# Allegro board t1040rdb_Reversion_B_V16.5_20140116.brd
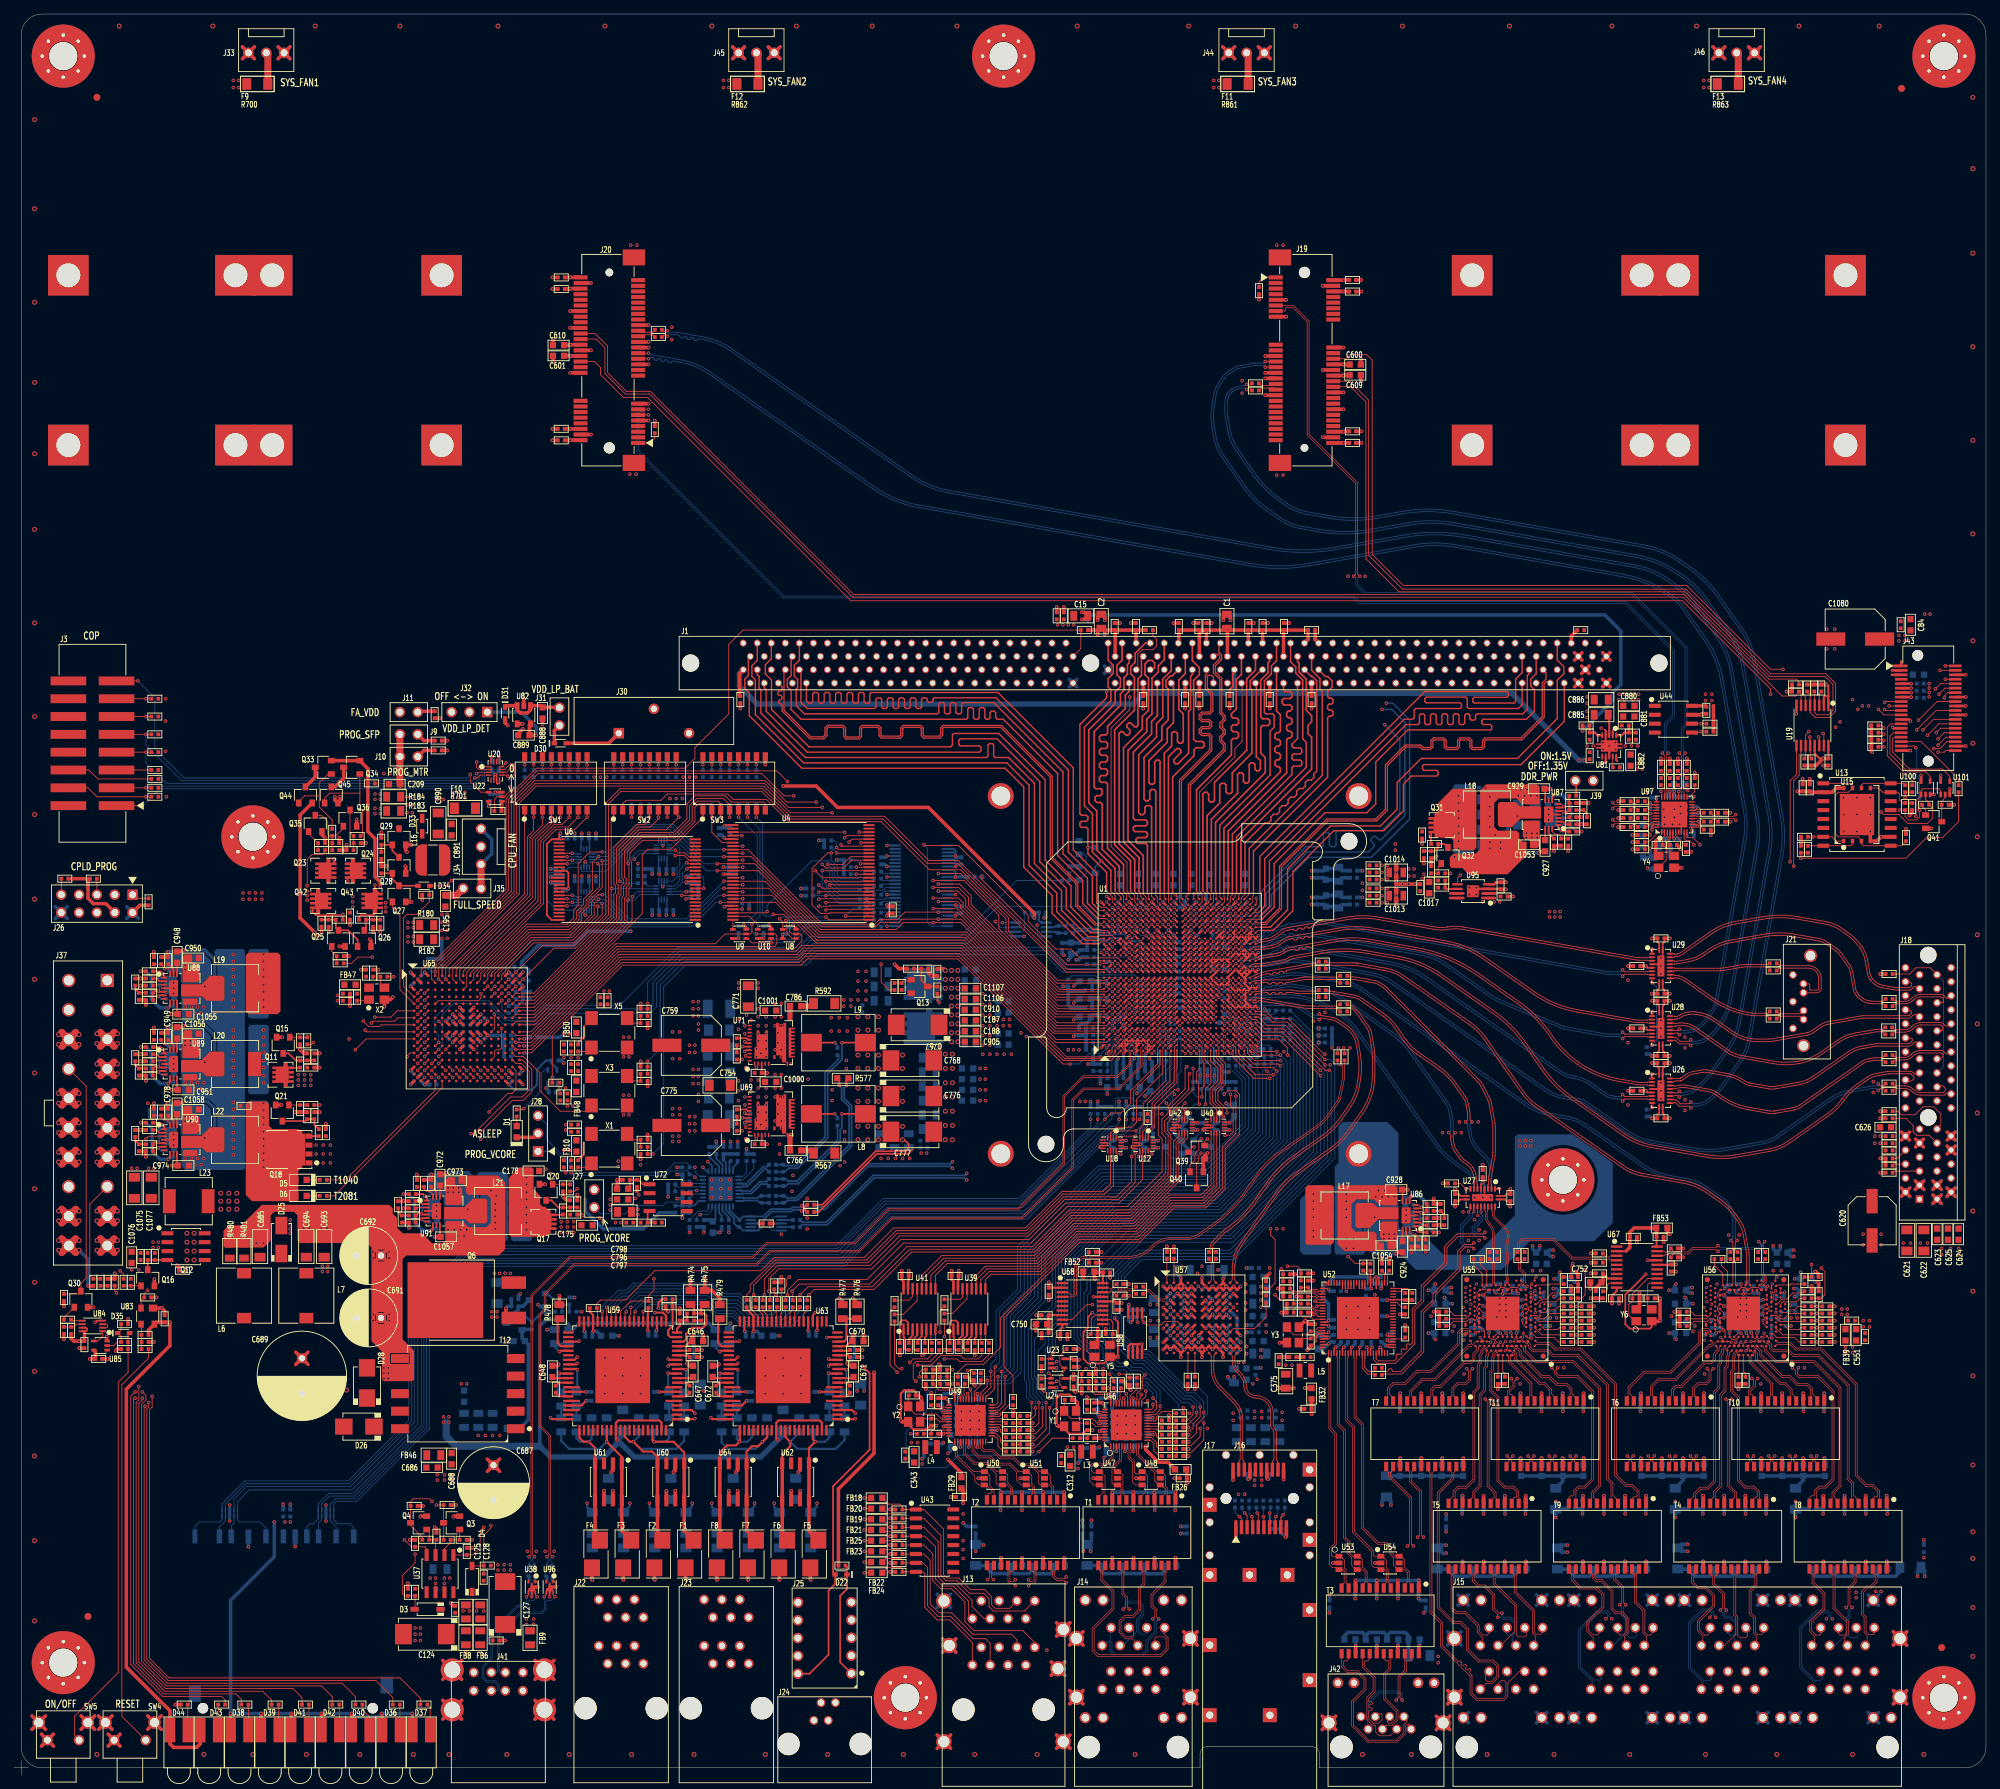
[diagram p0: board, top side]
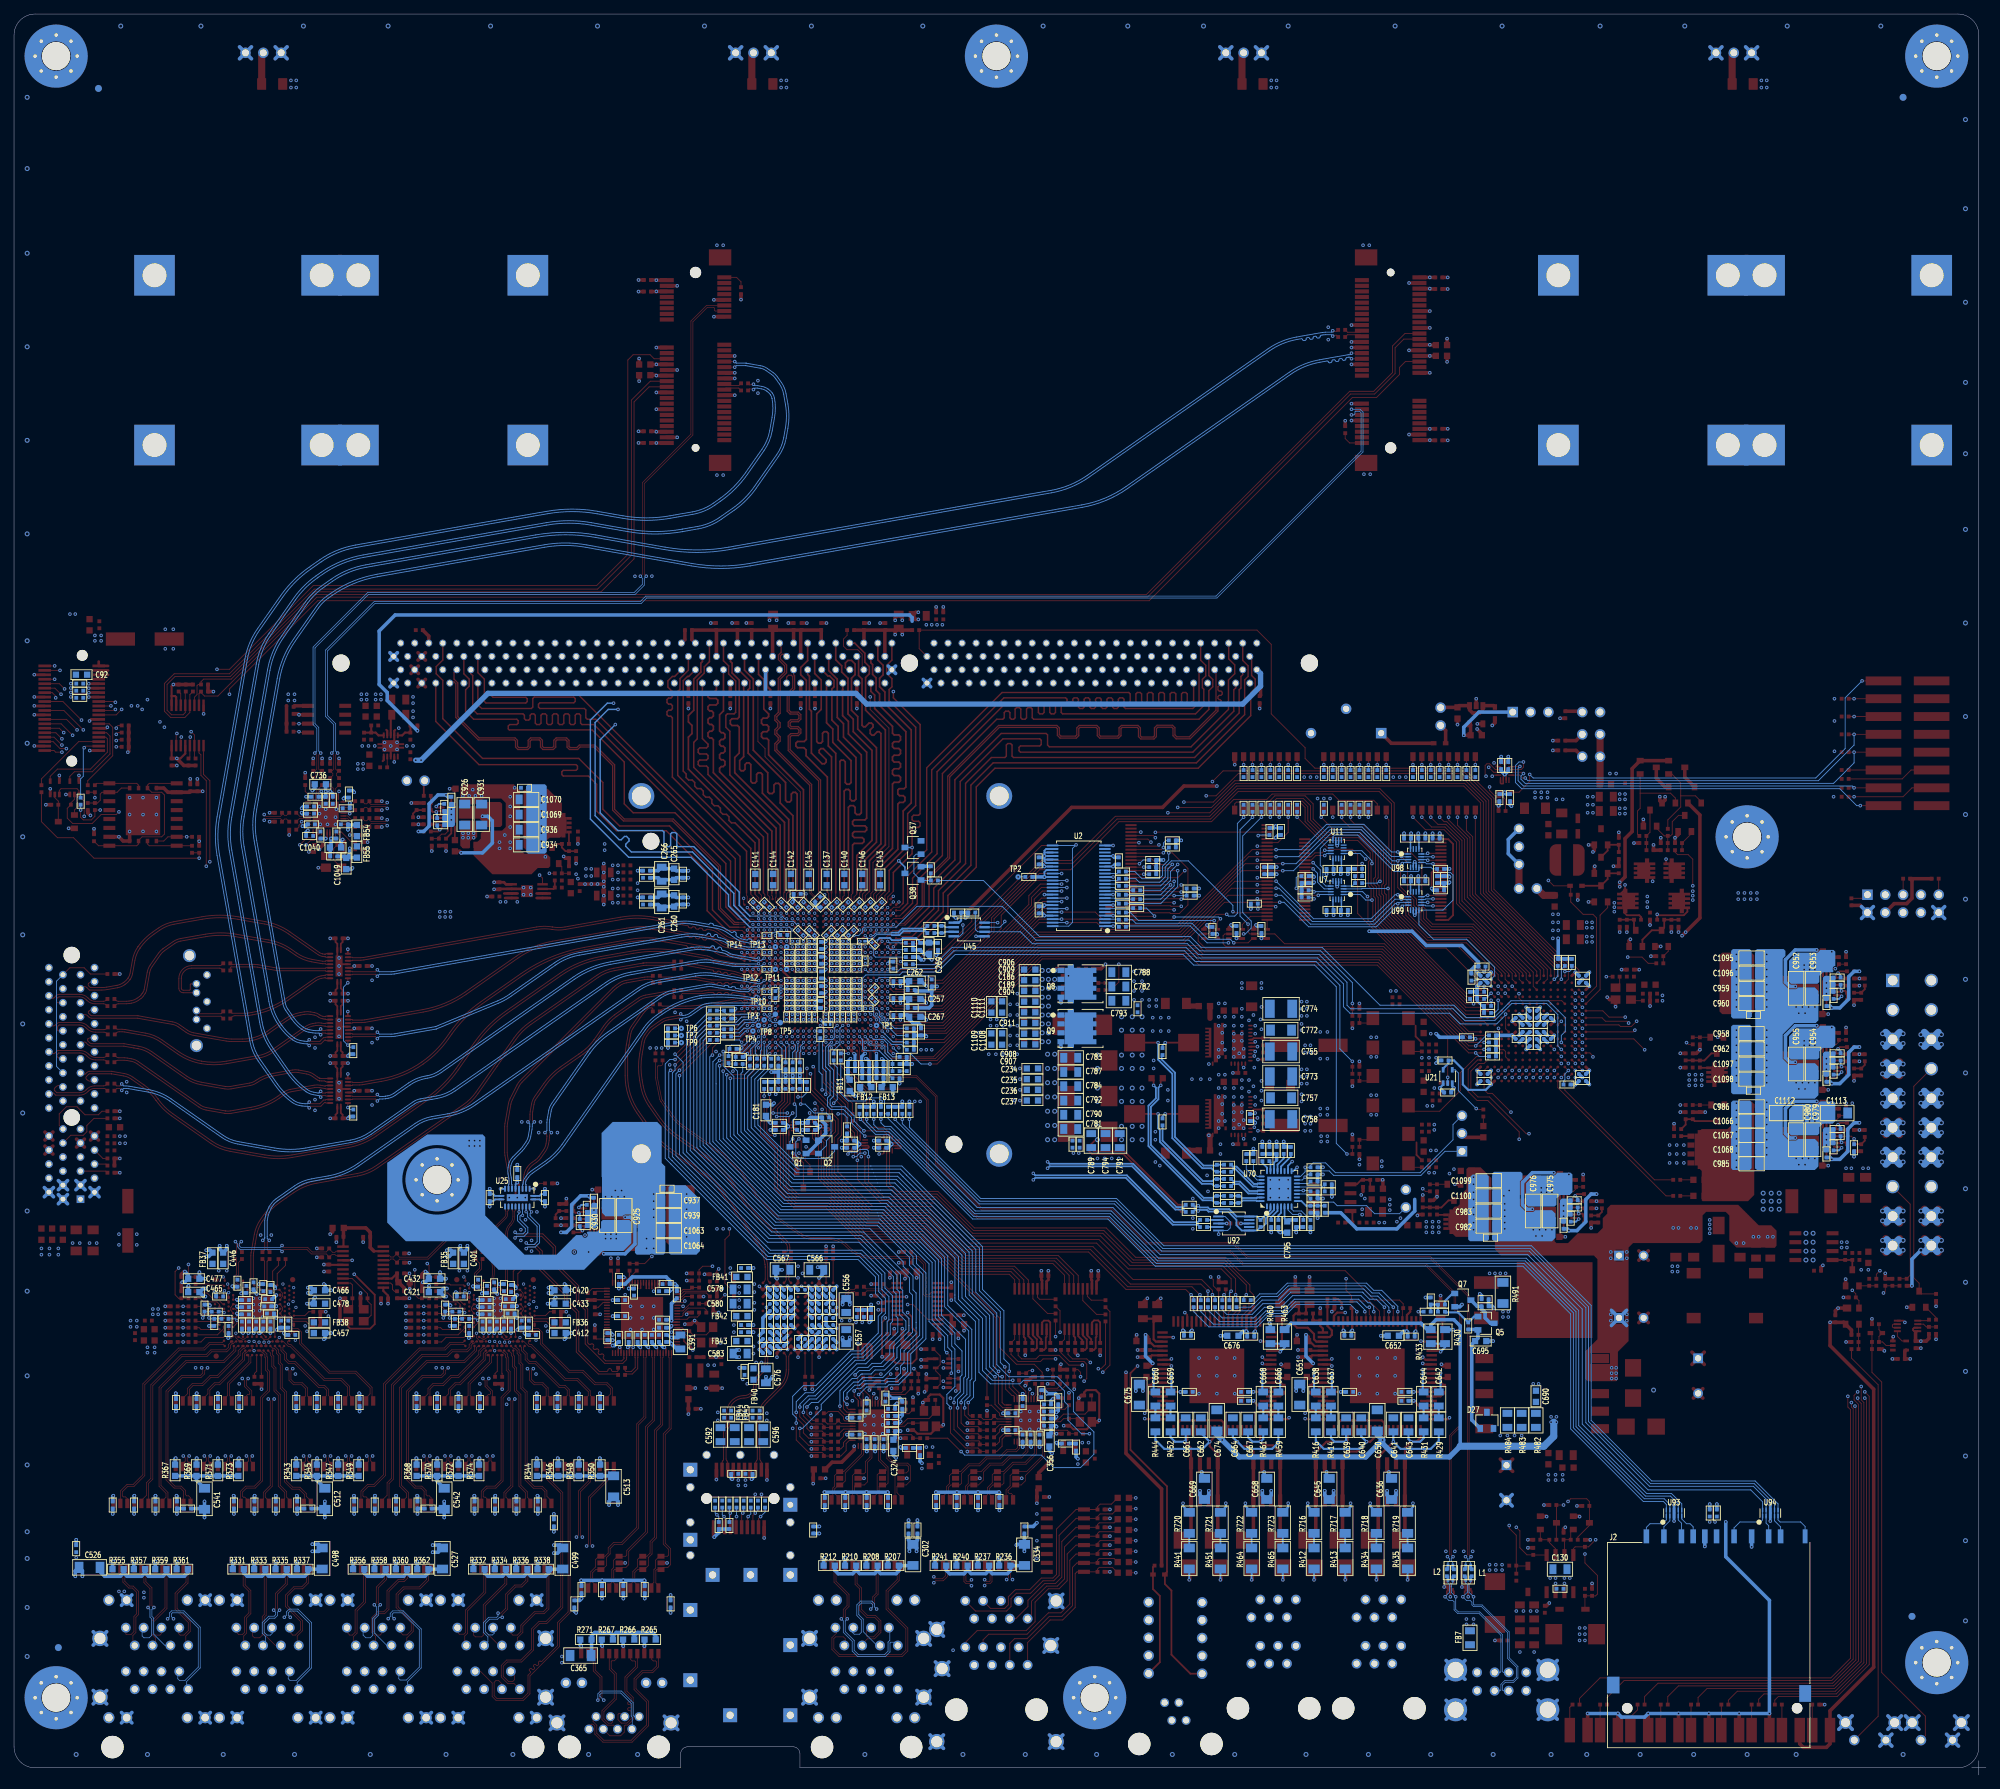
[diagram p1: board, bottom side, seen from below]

Outline 281.02 x 251.02 mm; copper layers: TOP, L2GND, L3SIG, L4PWR, L5PWR, L6SIG, L7GND, BOTTOM. Coordinates in mm from the lower left corner of the outline.
Outline path: 0,1.02 2.03,1.02 ; 1.02,2.03 1.02,0 ; 1.02,248.02 arc(1.89,250.14) 4.02,251.02 278.02,251.02 arc(280.14,250.14) 281.02,248.02 281.02,4.02 arc(280.14,1.89) 278.02,1.02 186.02,1.02 186.02,3.02 arc(185.72,3.72) 185.02,4.02 170.02,4.02 arc(169.31,3.72) 169.02,3.02 169.02,1.02 4.02,1.02 arc(1.89,1.89) 1.02,4.02 1.02,248.02

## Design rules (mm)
net group 1V05_EC1_AVDD: nets 1V05_EC1_DVDD N16973842
net group 1V05_EC2_AVDD: nets 1V05_EC2_DVDD N16880820
net group 1V05_SG_AVDD: nets 1V05_SG_DVDD N16909742
net group 1V8_0641_VDD: nets 1V8_0641_VDDA 1V8_0641_VDDXTAL
net group CKE_ISO_EN: nets CKE_ISO_EN N20553507
net group CPLD_REFCLK: nets CPLD_REFCLK N19163046
net group DDR_REFCLK: nets DDR_REFCLK N17232338
net group DDRPWR_EN_N: nets DDRPWR_EN_N N19623885
net group EC1_GTXCLK: nets EC1_GTXCLK N17060054
net group EC1_INT_N: nets EC1_INT_N N16974631
net group EC1_LED0: nets EC1_LED0 N16974572
net group EC1_LED1: nets EC1_LED1 N16974538
net group EC1_MDI0: nets EC1_MDI0_N EC1_MDI0_P
net group EC1_MDI1: nets EC1_MDI1_N EC1_MDI1_P
net group EC1_MDI2: nets EC1_MDI2_N EC1_MDI2_P
net group EC1_MDI3: nets EC1_MDI3_N EC1_MDI3_P
net group EC1_MDX0: nets EC1_MDX0_N EC1_MDX0_P
net group EC1_MDX1: nets EC1_MDX1_N EC1_MDX1_P
net group EC1_MDX2: nets EC1_MDX2_N EC1_MDX2_P
net group EC1_MDX3: nets EC1_MDX3_N EC1_MDX3_P
net group EC1_PME_N: nets EC1_PME_N N16975158
net group EC1_REFCLK: nets EC1_REFCLK N16975047
net group EC1_RST_N: nets EC1_RST_N N16974885
net group EC1_RXCLK: nets EC1_RXCLK N16974061
net group EC1_RXCTL: nets EC1_RXCTL N16974138
net group EC1_RXD0: nets EC1_RXD0 N16974094
net group EC1_RXD1: nets EC1_RXD1 N16974110
net group EC1_RXD2: nets EC1_RXD2 N16974123
net group EC1_RXD3: nets EC1_RXD3 N16974136
net group EC1_TXCTL: nets EC1_TXCTL N17059985
net group EC1_TXD0: nets EC1_TXD0 N17059735
net group EC1_TXD1: nets EC1_TXD1 N17059733
net group EC1_TXD2: nets EC1_TXD2 N17059734
net group EC1_TXD3: nets EC1_TXD3 N17059732
net group EC2_GTXCLK: nets EC2_GTXCLK N17059152
net group EC2_INT_N: nets EC2_INT_N N16871038
net group EC2_LED0: nets EC2_LED0 N16870890
net group EC2_LED1: nets EC2_LED1 N16870844
net group EC2_MDI0: nets EC2_MDI0_N EC2_MDI0_P
net group EC2_MDI1: nets EC2_MDI1_N EC2_MDI1_P
net group EC2_MDI2: nets EC2_MDI2_N EC2_MDI2_P
net group EC2_MDI3: nets EC2_MDI3_N EC2_MDI3_P
net group EC2_MDX0: nets EC2_MDX0_N EC2_MDX0_P
net group EC2_MDX1: nets EC2_MDX1_N EC2_MDX1_P
net group EC2_MDX2: nets EC2_MDX2_N EC2_MDX2_P
net group EC2_MDX3: nets EC2_MDX3_N EC2_MDX3_P
net group EC2_PME_N: nets EC2_PME_N N16877780
net group EC2_REFCLK: nets EC2_REFCLK N16874872
net group EC2_RST_N: nets EC2_RST_N N16873350
net group EC2_RXCLK: nets EC2_RXCLK N16869850
net group EC2_RXCTL: nets EC2_RXCTL N16869978
net group EC2_RXD0: nets EC2_RXD0 N16869910
net group EC2_RXD1: nets EC2_RXD1 N16869938
net group EC2_RXD2: nets EC2_RXD2 N16869959
net group EC2_RXD3: nets EC2_RXD3 N16869976
net group EC2_TXCTL: nets EC2_TXCTL N17059149
net group EC2_TXD0: nets EC2_TXD0 N17059126
net group EC2_TXD1: nets EC2_TXD1 N17059132
net group EC2_TXD2: nets EC2_TXD2 N17059135
net group EC2_TXD3: nets EC2_TXD3 N17059138
net group EMI1_MDC_SLP: nets EMI1_MDC_SLP N17060498
net group EMI2_MDC: nets EMI2_MDC N17059643
net group EVDD_SEL: nets EVDD_SEL N20559490
net group FXO_LED: nets FXO_LED N18635664
net group FXS1_LED: nets FXS1_LED N18636371
net group FXS2_LED: nets FXS2_LED N18636375
net group FXS3_LED: nets FXS3_LED N18636077
net group FXS4_LED: nets FXS4_LED N18636082
net group IFC_A5: nets IFC_A5 N22257590
net group IFC_A6: nets IFC_A6 N22257592
net group IFC_A7: nets IFC_A7 N22257594
net group IFC_A8: nets IFC_A8 N22258216
net group IFC_A9: nets IFC_A9 N22258098
net group IFC_A10: nets IFC_A10 N22258100
net group IFC_A11: nets IFC_A11 N22258102
net group IFC_A12: nets IFC_A12 N22258104
net group IFC_A13: nets IFC_A13 N22258634
net group IFC_A14: nets IFC_A14 N22258636
net group IFC_A15: nets IFC_A15 N22258638
net group IFC_CLK: nets IFC_CLK N16821274
net group IOPWR_EN: nets IOPWR_EN N18273767
net group LED_STATUS: nets LED_STATUS N22361656
net group LED_T1040_DET: nets LED_T1040_DET N19293526
net group LED_T2081_DET: nets LED_T2081_DET N19295120
net group MPEX1_REFCLK_N: nets MPEX1_REFCLK_N N21105614
net group MPEX1_REFCLK_P: nets MPEX1_REFCLK_P N21105612
net group MPEX1_RX: nets MPEX1_RX_N MPEX1_RX_P
net group MPEX1_TX_N: nets MPEX1_TX_N N16984233
net group MPEX1_TX_P: nets MPEX1_TX_P N16984231
net group MPEX2_REFCLK_N: nets MPEX2_REFCLK_N N21105622
net group MPEX2_REFCLK_P: nets MPEX2_REFCLK_P N21105620
net group MPEX2_RX: nets MPEX2_RX_N MPEX2_RX_P
net group MPEX2_TX_N: nets MPEX2_TX_N N16985356
net group MPEX2_TX_P: nets MPEX2_TX_P N16985354
net group N16849665: nets N16849665 N16849667
net group N16849815: nets N16849815 N16849817
net group N16862407: nets N16862407 N16862837
net group N17055373: nets N17055373 N17055376
net group N17055394: nets N17055394 N17055396
net group N17055422: nets N17055422 N17055507
net group N17055459: nets N17055459 N17055529
net group N17055495: nets N17055419 N17055495
net group N17055527: nets N17055461 N17055527
net group N17056740: nets N17056740 N17056750
net group N17056764: nets N17056764 N17056766
net group N17056778: nets N17056778 N17056834
net group N17056796: nets N17056796 N17056846
net group N17056816: nets N17056776 N17056816
net group N17056844: nets N17056798 N17056844
net group N17321019: nets N17321001 N17321019
net group N17399246: nets N17399246 N17399288
net group N17401544: nets N17400346 N17401544
net group N17448841: nets N17448841 N17448842
net group N17448854: nets N17448854 N17448855
net group N17639958: nets N17639958 N17639964
net group N18271718: nets N18271718 N18271794
net group N18272050: nets N18272050 N18272126
net group N18272820: nets N18272820 N18272905
net group N18273181: nets N18273181 N18273262
net group N18562864: nets N17523697 N18562864
net group N18564716: nets N18564716 N18564801
net group N18566414: nets N18566414 N18566880
net group N18671728: nets N18671664 N18671728
net group N18671731: nets N18671661 N18671731
net group N19623883: nets N19623883 N19623968
net group N19645019: nets N19645019 N19645035
net group N19646930: nets N19646930 N19646940
net group N19648414: nets N19648414 N19648420
net group N19650272: nets N19650272 N19650282
net group N19651731: nets N19651731 N19651747
net group N19653218: nets N19653218 N19653234
net group N19673378: nets N19673378 N19673381
net group N19675149: nets N19675149 N19675151
net group N20559492: nets N20559492 N20559589
net group N20559669: nets N20559669 N20559724
net group N20562350: nets N17013374 N20562350
net group PEX_REFCLK_N: nets N22254282 PEX_REFCLK_N
net group PEX_REFCLK_P: nets N22254280 PEX_REFCLK_P
net group PEX_RX0: nets PEX_RX0_N PEX_RX0_P
net group PEX_RX1: nets PEX_RX1_N PEX_RX1_P
net group PEX_RX2: nets PEX_RX2_N PEX_RX2_P
net group PEX_RX3: nets PEX_RX3_N PEX_RX3_P
net group PEX_TX0_N: nets N16980532 PEX_TX0_N
net group PEX_TX0_P: nets N16980534 PEX_TX0_P
net group PEX_TX1_N: nets N16981085 PEX_TX1_N
net group PEX_TX1_P: nets N16981083 PEX_TX1_P
net group PEX_TX2_N: nets N16981144 PEX_TX2_N
net group PEX_TX2_P: nets N16981142 PEX_TX2_P
net group PEX_TX3_N: nets N16981215 PEX_TX3_N
net group PEX_TX3_P: nets N16981213 PEX_TX3_P
net group PROC_SPI_CLK: nets N17040696 PROC_SPI_CLK
net group PWR_GOOD: nets N18563122 PWR_GOOD
net group QSG1_INT_N: nets N17584869 QSG1_INT_N
net group QSG1_LED0: nets N17775429 QSG1_LED0
net group QSG1_LED1: nets N17775417 QSG1_LED1
net group QSG1_MDI0: nets QSG1_MDI0_N QSG1_MDI0_P
net group QSG1_MDI1: nets QSG1_MDI1_N QSG1_MDI1_P
net group QSG1_MDI2: nets QSG1_MDI2_N QSG1_MDI2_P
net group QSG1_MDI3: nets QSG1_MDI3_N QSG1_MDI3_P
net group QSG1_MDX0: nets QSG1_MDX0_N QSG1_MDX0_P
net group QSG1_MDX1: nets QSG1_MDX1_N QSG1_MDX1_P
net group QSG1_MDX2: nets QSG1_MDX2_N QSG1_MDX2_P
net group QSG1_MDX3: nets QSG1_MDX3_N QSG1_MDX3_P
net group QSG1_REFCLK_N: nets N17823659 QSG1_REFCLK_N
net group QSG1_REFCLK_P: nets N17823662 QSG1_REFCLK_P
net group QSG1_RST_N: nets N17629369 QSG1_RST_N
net group QSG2_INT_N: nets N17640717 QSG2_INT_N
net group QSG2_LED0: nets N17779761 QSG2_LED0
net group QSG2_LED1: nets N17779755 QSG2_LED1
net group QSG2_MDI0: nets QSG2_MDI0_N QSG2_MDI0_P
net group QSG2_MDI1: nets QSG2_MDI1_N QSG2_MDI1_P
net group QSG2_MDI2: nets QSG2_MDI2_N QSG2_MDI2_P
net group QSG2_MDI3: nets QSG2_MDI3_N QSG2_MDI3_P
net group QSG2_MDX0: nets QSG2_MDX0_N QSG2_MDX0_P
net group QSG2_MDX1: nets QSG2_MDX1_N QSG2_MDX1_P
net group QSG2_MDX2: nets QSG2_MDX2_N QSG2_MDX2_P
net group QSG2_MDX3: nets QSG2_MDX3_N QSG2_MDX3_P
net group QSG2_REFCLK_N: nets N17824163 QSG2_REFCLK_N
net group QSG2_REFCLK_P: nets N17824166 QSG2_REFCLK_P
net group QSG2_RST_N: nets N17640965 QSG2_RST_N
net group QSG3_LED0: nets N17780059 QSG3_LED0
net group QSG3_LED1: nets N17780053 QSG3_LED1
net group QSG3_MDI0: nets QSG3_MDI0_N QSG3_MDI0_P
net group QSG3_MDI1: nets QSG3_MDI1_N QSG3_MDI1_P
net group QSG3_MDI2: nets QSG3_MDI2_N QSG3_MDI2_P
net group QSG3_MDI3: nets QSG3_MDI3_N QSG3_MDI3_P
net group QSG3_MDX0: nets QSG3_MDX0_N QSG3_MDX0_P
net group QSG3_MDX1: nets QSG3_MDX1_N QSG3_MDX1_P
net group QSG3_MDX2: nets QSG3_MDX2_N QSG3_MDX2_P
net group QSG3_MDX3: nets QSG3_MDX3_N QSG3_MDX3_P
net group QSG4_LED0: nets N17780372 QSG4_LED0
net group QSG4_LED1: nets N17780366 QSG4_LED1
net group QSG4_MDI0: nets QSG4_MDI0_N QSG4_MDI0_P
net group QSG4_MDI1: nets QSG4_MDI1_N QSG4_MDI1_P
net group QSG4_MDI2: nets QSG4_MDI2_N QSG4_MDI2_P
net group QSG4_MDI3: nets QSG4_MDI3_N QSG4_MDI3_P
net group QSG4_MDX0: nets QSG4_MDX0_N QSG4_MDX0_P
net group QSG4_MDX1: nets QSG4_MDX1_N QSG4_MDX1_P
net group QSG4_MDX2: nets QSG4_MDX2_N QSG4_MDX2_P
net group QSG4_MDX3: nets QSG4_MDX3_N QSG4_MDX3_P
net group QSG5_LED0: nets N17788889 QSG5_LED0
net group QSG5_LED1: nets N17788879 QSG5_LED1
net group QSG5_MDI0: nets QSG5_MDI0_N QSG5_MDI0_P
net group QSG5_MDI1: nets QSG5_MDI1_N QSG5_MDI1_P
net group QSG5_MDI2: nets QSG5_MDI2_N QSG5_MDI2_P
net group QSG5_MDI3: nets QSG5_MDI3_N QSG5_MDI3_P
net group QSG5_MDX0: nets QSG5_MDX0_N QSG5_MDX0_P
net group QSG5_MDX1: nets QSG5_MDX1_N QSG5_MDX1_P
net group QSG5_MDX2: nets QSG5_MDX2_N QSG5_MDX2_P
net group QSG5_MDX3: nets QSG5_MDX3_N QSG5_MDX3_P
net group QSG6_LED0: nets N17788975 QSG6_LED0
net group QSG6_LED1: nets N17788969 QSG6_LED1
net group QSG6_MDI0: nets QSG6_MDI0_N QSG6_MDI0_P
net group QSG6_MDI1: nets QSG6_MDI1_N QSG6_MDI1_P
net group QSG6_MDI2: nets QSG6_MDI2_N QSG6_MDI2_P
net group QSG6_MDI3: nets QSG6_MDI3_N QSG6_MDI3_P
net group QSG6_MDX0: nets QSG6_MDX0_N QSG6_MDX0_P
net group QSG6_MDX1: nets QSG6_MDX1_N QSG6_MDX1_P
net group QSG6_MDX2: nets QSG6_MDX2_N QSG6_MDX2_P
net group QSG6_MDX3: nets QSG6_MDX3_N QSG6_MDX3_P
net group QSG7_LED0: nets N17789057 QSG7_LED0
net group QSG7_LED1: nets N17789051 QSG7_LED1
net group QSG7_MDI0: nets QSG7_MDI0_N QSG7_MDI0_P
net group QSG7_MDI1: nets QSG7_MDI1_N QSG7_MDI1_P
net group QSG7_MDI2: nets QSG7_MDI2_N QSG7_MDI2_P
net group QSG7_MDI3: nets QSG7_MDI3_N QSG7_MDI3_P
net group QSG7_MDX0: nets QSG7_MDX0_N QSG7_MDX0_P
net group QSG7_MDX1: nets QSG7_MDX1_N QSG7_MDX1_P
net group QSG7_MDX2: nets QSG7_MDX2_N QSG7_MDX2_P
net group QSG7_MDX3: nets QSG7_MDX3_N QSG7_MDX3_P
net group QSG8_LED0: nets N17787773 QSG8_LED0
net group QSG8_LED1: nets N17787749 QSG8_LED1
net group QSG8_MDI0: nets QSG8_MDI0_N QSG8_MDI0_P
net group QSG8_MDI1: nets QSG8_MDI1_N QSG8_MDI1_P
net group QSG8_MDI2: nets QSG8_MDI2_N QSG8_MDI2_P
net group QSG8_MDI3: nets QSG8_MDI3_N QSG8_MDI3_P
net group QSG8_MDX0: nets QSG8_MDX0_N QSG8_MDX0_P
net group QSG8_MDX1: nets QSG8_MDX1_N QSG8_MDX1_P
net group QSG8_MDX2: nets QSG8_MDX2_N QSG8_MDX2_P
net group QSG8_MDX3: nets QSG8_MDX3_N QSG8_MDX3_P
net group QSGMII1_RX: nets QSGMII1_RX_N QSGMII1_RX_P
net group QSGMII1_TX_N: nets N18629376 QSGMII1_TX_N
net group QSGMII1_TX_P: nets N18629379 QSGMII1_TX_P
net group QSGMII2_RX_N: nets N17082123 QSGMII2_RX_N
net group QSGMII2_RX_P: nets N17082121 QSGMII2_RX_P
net group QSGMII2_TX_N: nets N18629428 QSGMII2_TX_N
net group QSGMII2_TX_P: nets N18629431 QSGMII2_TX_P
net group SATA_RX_N: nets N18629885 SATA_RX_N
net group SATA_RX_P: nets N18629888 SATA_RX_P
net group SATA_TX_N: nets N18629823 SATA_TX_N
net group SATA_TX_P: nets N18629826 SATA_TX_P
net group SD_REFCLK1_N: nets N19620774 SD_REFCLK1_N
net group SD_REFCLK1_P: nets N19620777 SD_REFCLK1_P
net group SD_REFCLK2_N: nets N21105630 SD_REFCLK2_N
net group SD_REFCLK2_P: nets N21105628 SD_REFCLK2_P
net group SD_RX1_N: nets N17081957 SD_RX1_N
net group SD_RX1_P: nets N17081955 SD_RX1_P
net group SD_RX2_N: nets N17082045 SD_RX2_N
net group SD_RX2_P: nets N17082047 SD_RX2_P
net group SD_RX5: nets SD_RX5_N SD_RX5_P
net group SD_RX6: nets SD_RX6_N SD_RX6_P
net group SD_RX7: nets SD_RX7_N SD_RX7_P
net group SD_TX1: nets SD_TX1_N SD_TX1_P
net group SD_TX2: nets SD_TX2_N SD_TX2_P
net group SD_TX5: nets SD_TX5_N SD_TX5_P
net group SD_TX6: nets SD_TX6_N SD_TX6_P
net group SD_TX7: nets SD_TX7_N SD_TX7_P
net group SDHC_CLK: nets N17040868 SDHC_CLK
net group SENSEGND: nets N20075564 SENSEGND
net group SENSEGNDC: nets SENSEGNDC VCORE_VRTN1
net group SENSEVDD: nets N20075552 SENSEVDD
net group SENSEVDDC: nets SENSEVDDC VCORE_VSEN1
net group SFPP_RX: nets SFPP_RX_N SFPP_RX_P
net group SFPP_TX: nets SFPP_TX_N SFPP_TX_P
net group SG_INT_N: nets N16894418 SG_INT_N
net group SG_LED0: nets N16892215 SG_LED0
net group SG_LED1: nets N16892219 SG_LED1
net group SG_MDI0: nets SG_MDI0_N SG_MDI0_P
net group SG_MDI1: nets SG_MDI1_N SG_MDI1_P
net group SG_MDI2: nets SG_MDI2_N SG_MDI2_P
net group SG_MDI3: nets SG_MDI3_N SG_MDI3_P
net group SG_MDX0: nets SG_MDX0_N SG_MDX0_P
net group SG_MDX1: nets SG_MDX1_N SG_MDX1_P
net group SG_MDX2: nets SG_MDX2_N SG_MDX2_P
net group SG_MDX3: nets SG_MDX3_N SG_MDX3_P
net group SG_RST_N: nets N16900769 SG_RST_N
net group SGMII_RX: nets SGMII_RX_N SGMII_RX_P
net group SGMII_TX_N: nets N16899338 SGMII_TX_N
net group SGMII_TX_P: nets N16899326 SGMII_TX_P
net group SPI_CS3_SEL: nets N21824193 SPI_CS3_SEL
net group SYS_REFCLK: nets N17170143 SYS_REFCLK
net group SYS_REFCLK_N: nets N21105856 SYS_REFCLK_N
net group SYS_REFCLK_P: nets N21105862 SYS_REFCLK_P
net group T2081_EN: nets N18564718 T2081_EN
net group TEMP_DIODE_N: nets N18586247 TEMP_DIODE_N
net group TEMP_DIODE_P: nets N18586245 TEMP_DIODE_P
net group USB1_DM: nets N17013078 USB1_DM
net group USB1_DP: nets N17013042 USB1_DP
net group USB1_FLG_N: nets N17021121 USB1_FLG_N
net group USB2_DM: nets N17020482 USB2_DM
net group USB2_DP: nets N17020476 USB2_DP
net group USB2_FLG_N: nets N17021131 USB2_FLG_N
net group USB_REFCLK: nets N17033690 USB_REFCLK
net group VDD_EN_N: nets N18272048 VDD_EN_N
net group XFI_RX_N: nets N17081810 XFI_RX_N
net group XFI_RX_P: nets N17081807 XFI_RX_P
net group XFI_TX_N: nets N16930193 XFI_TX_N
net group XFI_TX_P: nets N16930196 XFI_TX_P
net group XG_LED0: nets N18648944 XG_LED0
net group XG_LED1: nets N18648948 XG_LED1
net group XG_REFCLK_N: nets N16936678 XG_REFCLK_N
net group XG_REFCLK_P: nets N16936676 XG_REFCLK_P
net group XG_RST_N: nets N16948831 XG_RST_N
net group 3V3_OSC_CPLD: nets N19163064
net group 5V0_USB1: nets USB1_VBUSCLMP
net group 5V0_USB2: nets USB2_VBUSCLMP
net group 12V_POTS: nets N16851731 N16862179 N16862426 POTS_SWOUT
net group CLS_SECLK: nets EMI1_MDC TDMA_RCK_CLK8_12 TDMA_TCK_CLK9 TDMB_RCK_CLK10 TDMB_TCK_CLK11
net group IFC_AVD: nets IFC_AVD IFC_PAR1 N22476599
net group IOPWR_EN_N: nets IOPWR_EN_N N18271716 N18272822 N18273179
net group N16849681: nets N16849681 N16849691 N16849695
net group N16850446: nets N16850380 N16850446 N16850448
net group N16850463: nets N16850382 N16850461 N16850463
net group N16850645: nets N16850645 N16850755 N17447447
net group N16870294: nets N16870294 N16870296 N16870306 N16870310 N16870330
net group N16891950: nets N16891950 N16891952 N16891962 N16891966 N16891978
net group N16974225: nets N16974225 N16974227 N16974244 N16974248 N16974260
net group N17447445: nets N16850577 N16850749 N17447445
net group N17448845: nets N17448845 N17448846 N17448848
net group N17448868: nets N17448864 N17448868 N17448869
net group N17448872: nets N17448865 N17448871 N17448872
net group N17448901: nets N17448901 N17448913 N17449053
net group N17449052: nets N17448897 N17448912 N17449052
net group N17582904: nets N17582904 N17582906 N17582916 N17582920 N17582932
net group N17632317: nets N17632317 N17632319 N17632321 N17632325 N17632337
net group N17632726: nets N17632726 N17632728 N17632740 N17632744 N17632760
net group N17633242: nets N17633242 N17633244 N17633254 N17633258 N17633270
net group N17787818: nets N17787818 N17787943 N17787947 N17787951 N17787955
net group N17787822: nets N17787822 N17788175 N17788179 N17788183 N17788187
net group N17787848: nets N17787848 N17788409 N17788413 N17788425 N17788429
net group N17787852: nets N17787852 N17788647 N17788651 N17788663 N17788667
net group N19644936: nets N19644936 N19644956 N19645192 N19645200 N19825990
net group N19646830: nets N19646830 N19646848 N19646866 N19647102
net group N19648275: nets N19648275 N19648310 N19648328 N19648572
net group N19650163: nets N19650163 N19650181 N19650199 N19650430
net group N19651628: nets N19651628 N19651646 N19651664 N19651895
net group N19653107: nets N19653107 N19653133 N19653151 N19653382
net group OVDD_OSC_DDR: nets N17232433
net group OVDD_OSC_USB: nets N17033815
net group POTS1_RING: nets N16850386 N19535325 POTS1_RING
net group POTS1_TIP: nets N16850384 N19535322 POTS1_TIP
net group POTS2_RING: nets N16850798 N19535364 POTS2_RING
net group POTS2_TIP: nets N16850778 N19535367 POTS2_TIP
net group POTS3_RING: nets N17448867 N19535165 POTS3_RING
net group POTS3_TIP: nets N17448866 N19535162 POTS3_TIP
net group POTS4_RING: nets N17448915 N19535242 POTS4_RING
net group POTS4_TIP: nets N17448914 N19535245 POTS4_TIP
net group POTS_RST_N: nets N16848537 N17448825 POTS_RST_N
net group POTS_SWIS: nets POTS_SWIS
net group POTS_TDM_CLK: nets N17481068 N17540556 N17540598 POTS_TDM_CLK
net group POTS_TDM_FS: nets N16861730 N17449051 POTS_TDM_FS
net group POTS_TDM_RXD: nets N16848026 N17448817 POTS_TDM_RXD
net group POTS_TDM_TXD: nets N16861709 N17449050 POTS_TDM_TXD
net group SPI_CLK: nets N17540577 N17540619 SPI_CLK
net group SPI_MISO: nets N16848601 N16864329 N17448833 SPI_MISO
net group SPI_MOSI: nets N16848521 N17448821 SPI_MOSI
net group VBH: nets N16859448 N17259940 N17449042 POTS_SWCMP POTSA_SWVSY POTSA_SWVSZ POTSB_SWVSY POTSB_SWVSZ
net group VCORE_ISEN1A: nets VCORE_IRTN1A
net group VCORE_ISEN1B: nets VCORE_IRTN1B
net group VCORE_SW1: nets N18675394 N18676216 N18677032 N19211889 VCORE_ISEN1A
net group VCORE_SW2: nets N18679447 N18679579 N18679604 N19212054 VCORE_ISEN1B

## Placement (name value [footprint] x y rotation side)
C1  22uF  [0805]  172.85 164.47 90 top
C2  22uF  [0805]  154.94 164.47 90 top
C3  0.1uF  [0402]  160.91 153.29 270 top
C4  0.1uF  [0402]  177.93 163.7 90 top
C5  0.1uF  [0402]  168.78 163.7 90 top
C6  0.1uF  [0402]  180.97 163.7 90 top
C7  0.1uF  [0402]  159.89 163.7 90 top
C8  0.1uF  [0402]  169.93 163.7 90 top
C9  0.1uF  [0402]  166.88 153.29 270 top
C10  0.1uF  [0402]  168.91 153.29 270 top
C11  0.1uF  [0402]  165.99 163.7 90 top
C12  0.1uF  [0402]  156.84 163.7 90 top
C13  0.1uF  [0402]  184.91 153.29 270 top
C14  0.1uF  [0402]  178.94 153.29 270 top
C15  22uF  [0805]  152.02 165.23 0 top
C16  0.1uF  [0402]  149.61 165.23 90 top
C17  0.1uF  [0402]  148.59 165.23 90 top
C18  0.1uF  [0402]  173.23 153.29 270 top
C19  0.1uF  [0402]  103.51 153.29 270 top
C20  0.1uF  [0402]  223.27 163.19 180 top
C21  0.1uF  [0201]  160.11 118.85 0 bottom
C22  0.01uF  [0201]  158.51 118.45 225 bottom
C23  0.1uF  [0402]  125.22 123.32 270 top
C24  0.1uF  [0402]  123.57 130.3 90 bottom
C25  0.1uF  [0402]  135 130.3 90 bottom
C26  0.1uF  [0402]  135 123.32 270 bottom
C27  1uF  [0402]  77.22 127.64 90 bottom
C28  0.1uF  [0402]  96.52 127.64 90 bottom
C29  0.1uF  [0402]  78.23 127.64 90 bottom
C30  0.1uF  [0402]  103.25 120.52 90 bottom
C31  0.1uF  [0402]  110.24 120.4 90 bottom
C32  0.1uF  [0402]  106.81 120.52 90 bottom
C33  1uF  [0402]  102.87 128.91 90 bottom
C34  0.1uF  [0402]  101.85 128.91 90 bottom
C35  0.1uF  [0402]  100.46 134.49 270 bottom
C36  1uF  [0402]  255.91 140.72 90 top
C37  0.1uF  [0402]  254.89 140.72 90 top
C38  1uF  [0402]  38.35 37.34 90 bottom
C39  0.1uF  [0402]  39.37 37.34 90 bottom
C40  0.1uF  [0402]  161.8 90.42 180 bottom
C41  0.1uF  [0402]  161.8 89.41 180 bottom
C42  0.1uF  [0402]  157.23 90.42 180 bottom
C43  0.1uF  [0402]  157.23 89.41 180 bottom
C48  0.1uF  [0402]  258.57 144.4 270 top
C49  0.1uF  [0402]  68.07 143.89 270 bottom
C50  0.1uF  [0402]  69.09 143.89 270 bottom
C51  0.1uF  [0402]  67.82 139.32 90 bottom
C52  0.1uF  [0402]  76.71 97.28 180 bottom
C53  0.1uF  [0402]  69.34 139.32 90 bottom
C54  0.1uF  [0402]  77.09 101.85 0 bottom
C55  10pF  [0402]  177.67 102.36 0 bottom
C56  10pF  [0402]  179.32 107.82 180 bottom
C57  0.1uF  [0402]  151 55.88 270 top
C58  0.1uF  [0402]  151 58.67 270 top
C59  0.1uF  [0402]  189.48 108.84 180 top
C60  0.1uF  [0402]  189.48 109.86 180 top
C61  0.1uF  [0402]  189.48 113.92 180 top
C62  0.1uF  [0402]  186.44 114.94 180 top
C63  0.1uF  [0402]  186.44 110.87 180 top
C64  0.1uF  [0402]  186.44 111.89 180 top
C65  0.1uF  [0402]  189.48 112.9 180 top
C66  0.1uF  [0402]  186.44 115.95 180 top
C67  0.1uF  [0402]  188.59 102.36 90 top
C68  0.1uF  [0402]  189.61 102.36 90 top
C69  0.01uF  [0402]  209.3 85.73 90 bottom
C70  0.01uF  [0402]  213.23 82.3 270 bottom
C71  0.01uF  [0402]  205.36 82.3 270 bottom
C72  0.01uF  [0402]  234.7 101.47 0 top
C73  0.01uF  [0402]  231.27 97.54 180 top
C74  0.01uF  [0402]  234.7 93.6 0 top
C75  0.01uF  [0402]  205.36 82.3 270 top
C76  0.01uF  [0402]  213.23 82.3 270 top
C77  0.01uF  [0402]  209.3 85.73 90 top
C78  0.01uF  [0402]  234.7 102.49 0 top
C79  0.01uF  [0402]  231.27 106.43 180 top
C80  0.01uF  [0402]  234.7 110.36 0 top
C81  0.01uF  [0402]  234.7 119.25 0 top
C82  0.01uF  [0402]  234.7 111.38 0 top
C83  0.01uF  [0402]  231.27 115.32 180 top
C84  0.1uF  [0603]  270.26 163.96 90 top
C85  0.01uF  [0402]  268.86 163.96 90 top
C92  10uF  [0603]  271.4 156.84 0 bottom
C93  0.1uF  [0402]  271.65 155.57 0 bottom
C94  0.1uF  [0402]  271.65 154.56 0 bottom
C124  100uF  [7343]  58.55 20.07 180 top
C125  10uF  [0805]  64.39 23.24 90 top
C126  1000pF  [0402]  62.86 23.62 90 top
C127  100uF  [7343]  69.98 24.51 90 top
C128  10uF  [0805]  66.42 23.24 90 top
C129  1000pF  [0402]  68.71 19.18 0 top
C130  10uF  [0805]  60.71 29.34 180 bottom
C131  0.1uF  [0402]  60.71 26.54 180 bottom
C132  10pF  [0402]  89.79 90.55 0 top
C133  0.1uF  [0402]  78.36 87.12 270 top
C134  0.01uF  [0402]  79.38 87.12 270 top
C135  1uF  [0402]  79.88 91.69 180 top
C136  0.1uF  [0402]  79.88 92.71 180 top
C137  10uF  [0603]  165.23 127.64 90 bottom
C138  2.2uF  [0402]  161.67 100.33 180 bottom
C139  0.01uF  [0402]  162.51 124.05 315 bottom
C140  10uF  [0603]  162.69 127.64 90 bottom
C141  10uF  [0603]  175.39 127.64 90 bottom
C142  10uF  [0603]  170.31 127.64 90 bottom
C143  10uF  [0603]  157.61 127.64 90 bottom
C144  10uF  [0603]  172.85 127.64 90 bottom
C145  10uF  [0603]  167.77 127.64 90 bottom
C146  10uF  [0603]  160.15 127.64 90 bottom
C147  0.1uF  [0201]  162.51 110.04 0 bottom
C148  0.1uF  [0201]  162.51 109.24 0 bottom
C149  2.2uF  [0402]  161.67 101.35 180 bottom
C150  0.1uF  [0402]  171.32 124.05 225 bottom
C151  0.1uF  [0402]  164.11 124.05 315 bottom
C152  0.1uF  [0402]  175.32 124.05 225 bottom
C153  0.1uF  [0402]  168.12 124.05 225 bottom
C154  0.1uF  [0402]  160.91 124.05 315 bottom
C155  0.1uF  [0402]  157.71 124.05 315 bottom
C156  0.1uF  [0402]  163.31 120.05 135 bottom
C157  0.1uF  [0402]  167.32 120.05 45 bottom
C158  0.1uF  [0201]  161.31 108.04 270 bottom
C159  0.1uF  [0201]  162.11 108.04 270 bottom
C160  3000pF  [0402]  159.64 101.35 0 bottom
C161  2.2uF  [0402]  159.64 99.31 0 bottom
C162  2.2uF  [0402]  159.64 100.33 0 bottom
C163  0.01uF  [0402]  169.72 124.05 225 bottom
C164  0.01uF  [0402]  173.72 124.05 225 bottom
C165  0.01uF  [0402]  159.31 124.05 315 bottom
C166  0.01uF  [0402]  161.71 120.05 135 bottom
C167  0.01uF  [0402]  168.92 120.05 45 bottom
C168  0.01uF  [0402]  164.92 120.05 135 bottom
C169  0.01uF  [0402]  165.72 124.05 315 bottom
C170  0.1uF  [0201]  160.91 110.04 180 bottom
C171  0.1uF  [0201]  160.91 109.24 180 bottom
C172  3000pF  [0402]  157.61 101.35 0 bottom
C173  2.2uF  [0402]  157.61 100.33 0 bottom
C174  2.2uF  [0402]  157.61 99.31 0 bottom
C175  10uF  [0603]  81.66 78.36 0 top
C176  0.1uF  [0201]  170.12 108.04 270 bottom
C177  0.1uF  [0201]  169.32 108.04 270 bottom
C178  10uF  [0603]  74.04 86.11 0 top
C179  0.1uF  [0201]  167.72 108.04 270 bottom
C180  0.1uF  [0201]  168.52 108.04 270 bottom
C181  10uF  [0603]  173.86 94.74 90 bottom
C182  0.1uF  [0201]  165.32 108.04 270 bottom
C183  0.1uF  [0201]  166.92 108.04 270 bottom
C184  0.1uF  [0201]  163.71 108.04 270 bottom
C185  0.1uF  [0201]  162.91 108.04 270 bottom
C186  22uF  [0603]  136.27 111.76 0 bottom
C187  22uF  [0603]  136.27 107.57 0 top
C188  22uF  [0603]  136.27 106.05 0 top
C189  22uF  [0603]  136.27 110.24 0 bottom
C192  0.1uF  [0201]  158.53 112.05 135 bottom
C195  10uF  [0603]  61.47 124.59 90 top
C196  0.1uF  [0201]  160.91 115.65 180 bottom
C197  0.1uF  [0201]  160.91 114.85 180 bottom
C198  0.1uF  [0201]  160.91 113.25 180 bottom
C199  0.1uF  [0201]  160.91 118.05 180 bottom
C200  0.1uF  [0201]  162.51 118.05 0 bottom
C201  0.1uF  [0201]  162.51 118.85 180 bottom
C202  0.1uF  [0201]  168.92 113.25 0 bottom
C203  0.1uF  [0201]  168.92 115.65 0 bottom
C204  0.1uF  [0201]  167.32 114.85 180 bottom
C205  0.1uF  [0201]  168.92 117.25 0 bottom
C206  0.1uF  [0201]  164.11 117.25 180 bottom
C207  0.1uF  [0201]  168.92 112.44 180 bottom
C208  0.1uF  [0201]  158.53 110.45 225 bottom
C209  10uF  [0603]  54.23 141.22 180 top
C210  0.1uF  [0201]  160.91 112.44 180 bottom
C211  0.1uF  [0201]  160.91 111.64 180 bottom
C212  0.1uF  [0201]  170.52 113.25 0 bottom
C213  0.1uF  [0201]  167.32 113.25 0 bottom
C214  0.1uF  [0201]  168.92 114.85 180 bottom
C215  0.1uF  [0201]  164.11 118.85 180 bottom
C216  0.1uF  [0201]  168.92 116.45 180 bottom
C217  0.1uF  [0201]  162.51 117.25 180 bottom
C218  0.1uF  [0201]  167.32 118.85 0 bottom
C219  0.1uF  [0201]  167.32 116.45 180 bottom
C220  0.1uF  [0201]  160.91 110.84 180 bottom
C222  0.1uF  [0201]  159.71 116.05 270 bottom
C223  0.1uF  [0201]  164.11 118.05 0 bottom
C224  0.1uF  [0201]  167.32 118.05 180 bottom
C225  0.1uF  [0201]  167.32 117.25 0 bottom
C226  0.1uF  [0201]  168.92 118.05 180 bottom
C227  1500pF  [0201]  167.32 115.65 0 bottom
C228  1500pF  [0201]  167.32 111.64 0 bottom
C229  1500pF  [0201]  162.51 116.45 0 bottom
C230  1500pF  [0201]  167.32 112.44 180 bottom
C232  0.1uF  [0201]  159.31 109.24 180 bottom
C234  22uF  [0603]  135.89 100.71 180 bottom
C235  22uF  [0603]  135.89 99.19 180 bottom
C236  22uF  [0603]  135.89 97.66 180 bottom
C237  22uF  [0603]  135.89 96.14 180 bottom
C238  1uF  [0402]  166.02 109.84 270 bottom
C239  1uF  [0402]  129.16 89.92 270 bottom
C240  1uF  [0402]  130.17 89.92 270 bottom
C241  1uF  [0402]  120.9 109.22 90 bottom
C242  2.2uF  [0402]  193.67 126.37 180 top
C243  2.2uF  [0402]  193.67 124.33 180 top
C244  3000pF  [0402]  193.67 125.35 180 top
C245  0.1uF  [0201]  169.72 118.85 180 bottom
C246  0.1uF  [0201]  170.52 117.25 0 bottom
C247  0.1uF  [0201]  170.52 116.45 0 bottom
C248  0.1uF  [0201]  170.52 115.65 0 bottom
C249  2.2uF  [0402]  193.67 128.65 180 top
C250  2.2uF  [0402]  193.67 129.67 180 top
C251  3000pF  [0402]  193.67 127.64 180 top
C252  0.1uF  [0201]  173.73 111.65 0 bottom
C253  0.1uF  [0201]  173.72 114.85 0 bottom
C254  0.1uF  [0201]  173.72 119.65 0 bottom
C255  0.1uF  [0201]  173.72 117.25 0 bottom
C256  0.1uF  [0201]  165.02 106.94 180 bottom
C257  10uF  [0603]  152.65 110.62 180 bottom
C258  1uF  [0402]  155.19 110.74 0 bottom
C259  3000pF  [0402]  185.67 124.59 90 bottom
C260  4.7uF  [0603]  186.94 124.59 90 bottom
C261  47uF  [0805]  188.72 124.59 90 bottom
C262  10uF  [0603]  152.65 113.16 180 bottom
C263  1uF  [0402]  155.19 113.16 0 bottom
C264  3000pF  [0402]  185.67 128.4 90 bottom
C265  4.7uF  [0603]  186.94 128.4 90 bottom
C266  47uF  [0805]  188.72 128.4 90 bottom
C267  10uF  [0603]  152.65 108.08 180 bottom
C268  1uF  [0402]  155.19 108.33 0 bottom
C269  10uF  [0603]  150.62 117.86 270 bottom
C270  1uF  [0402]  151.89 118.11 270 bottom
C271  0.1uF  [0402]  134.62 61.09 270 top
C272  0.1uF  [0402]  134.11 71.12 0 top
C273  0.1uF  [0402]  133.35 61.09 270 top
C274  0.1uF  [0402]  135.89 61.09 270 top
C275  0.1uF  [0402]  136.91 61.09 270 top
C276  100pF  [0402]  126.11 34.04 180 top
C277  100pF  [0402]  126.11 36.58 180 top
C278  100pF  [0402]  126.11 35.31 180 top
C279  100pF  [0402]  126.11 37.85 180 top
C280  0.1uF  [0402]  171.96 92.96 180 bottom
C281  0.1uF  [0402]  171.96 91.95 180 bottom
C282  0.1uF  [0402]  167.39 92.96 180 bottom
C283  0.1uF  [0402]  167.39 91.95 180 bottom
C284  0.1uF  [0402]  128.78 61.09 270 top
C285  0.1uF  [0402]  127.51 61.09 270 top
C286  0.1uF  [0402]  127 71.12 0 top
C287  0.1uF  [0402]  126.24 61.09 270 top
C288  0.1uF  [0402]  129.79 61.09 270 top
C289  100pF  [0402]  126.11 32.77 180 top
C290  100pF  [0402]  126.11 28.96 180 top
C291  100pF  [0402]  126.11 31.5 180 top
C292  100pF  [0402]  126.11 30.23 180 top
C293  0.1uF  [0402]  241.17 151.76 270 top
C294  1000pF  [0402]  148.84 120.52 90 bottom
C295  0.1uF  [0402]  146.56 122.94 0 bottom
C296  0.01uF  [0402]  156.46 38.99 90 bottom
C297  0.1uF  [0402]  166.62 42.29 180 top
C298  0.01uF  [0402]  159.51 38.99 90 bottom
C299  0.01uF  [0402]  162.56 38.99 90 bottom
C300  10pF  [0402]  164.08 50.55 180 top
C301  0.01uF  [0402]  165.48 38.99 90 bottom
C302  1000pF  [1206]  152.91 31.37 90 bottom
C303  10pF  [0402]  153.42 48.01 0 top
C304  27pF  [0402]  150.24 53.47 0 top
C305  27pF  [0402]  152.91 49.66 270 top
C306  0.1uF  [0402]  153.54 34.92 270 bottom
C307  470pF  [0402]  152.65 57.15 0 top
C308  470pF  [0402]  154.69 57.15 180 top
C309  1000pF  [0402]  151.89 46.1 270 bottom
C310  0.01uF  [0402]  167.13 34.92 270 bottom
C312  4.7uF  [0603]  150.5 44.83 270 top
C313  0.1uF  [0402]  149.22 44.96 270 top
C314  0.1uF  [0402]  161.04 48.51 180 bottom
C315  0.1uF  [0402]  161.04 50.93 180 bottom
C316  0.1uF  [0402]  156.84 53.72 270 bottom
C317  0.1uF  [0402]  159.51 52.45 270 bottom
C319  0.1uF  [0402]  155.96 50.16 0 bottom
C320  0.1uF  [0402]  155.96 52.2 0 bottom
C321  0.1uF  [0402]  159.51 47.37 90 bottom
C322  0.1uF  [0402]  155.96 51.18 0 bottom
C323  0.1uF  [0402]  157.1 47.37 90 bottom
C324  4.7uF  [0603]  155.7 46.99 270 bottom
C325  0.1uF  [0402]  155.96 49.02 0 bottom
C326  0.1uF  [0402]  158.37 47.37 90 bottom
C328  0.01uF  [0402]  140.59 38.99 90 bottom
C329  0.1uF  [0402]  134.75 39.62 180 top
C330  0.01uF  [0402]  143.64 38.99 90 bottom
C331  10pF  [0402]  141.86 51.18 180 top
C332  0.01uF  [0402]  146.69 38.99 90 bottom
C333  0.01uF  [0402]  149.61 38.99 90 bottom
C334  1000pF  [1206]  137.03 31.37 90 bottom
C335  10pF  [0402]  131.19 48.64 0 top
C336  0.1uF  [0402]  137.03 34.92 270 bottom
C337  470pF  [0402]  130.43 57.78 0 top
C338  470pF  [0402]  132.46 57.78 180 top
C339  27pF  [0402]  128.02 54.1 0 top
C340  27pF  [0402]  130.68 50.29 270 top
C341  1000pF  [0402]  129.67 46.74 270 bottom
C342  0.01uF  [0402]  152.27 34.92 270 bottom
C343  4.7uF  [0603]  128.27 45.34 270 top
C344  0.1uF  [0402]  127 45.59 270 top
C346  0.1uF  [0402]  138.81 51.56 180 bottom
C347  0.1uF  [0402]  138.81 49.15 180 bottom
C348  0.1uF  [0402]  137.29 53.09 270 bottom
C349  0.1uF  [0402]  134.62 54.36 270 bottom
C350  0.1uF  [0402]  133.73 50.8 0 bottom
C351  0.1uF  [0402]  133.73 52.83 0 bottom
C353  0.1uF  [0402]  137.29 48.01 90 bottom
C354  0.1uF  [0402]  134.87 48.01 90 bottom
C355  0.1uF  [0402]  133.73 51.82 0 bottom
C356  4.7uF  [0603]  133.48 47.62 270 bottom
C357  0.1uF  [0402]  133.73 49.78 0 bottom
C358  0.1uF  [0402]  136.14 48.01 90 bottom
C360  0.01uF  [0402]  197.23 26.42 90 bottom
C361  0.1uF  [0402]  184.4 52.2 180 top
C362  0.01uF  [0402]  191.13 26.42 90 bottom
C363  0.01uF  [0402]  200.15 26.42 90 bottom
C364  0.01uF  [0402]  194.18 26.42 90 bottom
C365  1000pF  [1206]  200.28 17.02 0 bottom
C366  0.1uF  [0402]  194.44 57.02 0 top
C367  0.1uF  [0402]  194.44 58.04 0 top
C368  0.1uF  [0402]  187.45 24.38 270 bottom
C369  470pF  [0402]  181.36 71.37 0 top
C370  470pF  [0402]  183.9 71.5 0 top
C371  0.01uF  [0402]  201.17 24.38 270 bottom
C372  27pF  [0402]  184.78 63.75 90 top
C373  27pF  [0402]  184.78 61.72 270 top
C374  1000pF  [0402]  182.25 59.56 180 top
C375  22uF  [0805]  181.23 56.13 270 top
C376  0.1uF  [0402]  180.21 59.05 90 top
C377  0.1uF  [0402]  188.09 69.98 0 bottom
C378  0.1uF  [0402]  194.82 70.48 90 bottom
C381  0.1uF  [0402]  188.59 63.75 0 bottom
C382  0.1uF  [0402]  188.59 68.96 0 bottom
C383  0.1uF  [0402]  192.66 68.83 270 bottom
C384  0.1uF  [0402]  189.1 62.23 90 bottom
C385  0.1uF  [0402]  191.13 62.23 90 bottom
C386  0.1uF  [0402]  188.59 64.9 0 bottom
C388  0.1uF  [0402]  194.82 62.23 90 bottom
C389  0.1uF  [0402]  192.15 62.23 90 bottom
C390  0.1uF  [0402]  193.42 62.23 90 bottom
C391  22uF  [0805]  186.05 61.72 270 bottom
C392  0.1uF  [0402]  190.12 62.23 90 bottom
C393  0.1uF  [0402]  188.09 62.23 270 bottom
C398  0.1uF  [0402]  194.44 67.69 180 bottom
C399  0.1uF  [0402]  194.44 65.41 180 bottom
C400  0.1uF  [0402]  210.31 74.04 270 top
C401  10uF  [0603]  216.92 73.66 90 bottom
C402  1uF  [0402]  211.2 69.47 270 bottom
C403  0.1uF  [0402]  214.25 64.14 90 bottom
C404  0.1uF  [0402]  210.19 64.14 90 bottom
C405  0.1uF  [0402]  211.33 74.04 270 top
C406  0.1uF  [0402]  216.15 63.5 90 bottom
C407  0.1uF  [0402]  212.22 64.14 90 bottom
C410  0.1uF  [0402]  215.26 74.04 270 top
C411  0.1uF  [0402]  214.25 74.04 270 top
C412  10uF  [0603]  203.2 62.99 180 bottom
C413  1uF  [0402]  207.64 64.26 90 bottom
C414  0.1uF  [0402]  213.23 64.14 90 bottom
C415  0.1uF  [0402]  211.2 64.14 90 bottom
C416  0.1uF  [0402]  208.66 64.26 90 bottom
C420  10uF  [0603]  203.2 69.09 180 bottom
C421  10uF  [0603]  221.11 68.83 0 bottom
C422  1uF  [0402]  212.6 69.72 90 bottom
C423  0.1uF  [0402]  210.19 65.79 0 bottom
C424  0.1uF  [0402]  210.19 69.34 270 bottom
C425  0.1uF  [0402]  213.74 66.68 180 bottom
C432  10uF  [0603]  221.11 70.74 180 bottom
C433  10uF  [0603]  203.2 67.18 0 bottom
C434  1uF  [0402]  213.74 65.66 180 bottom
C435  0.1uF  [0402]  210.44 67.82 0 bottom
C436  0.1uF  [0402]  213.74 67.69 180 bottom
C437  0.1uF  [0402]  210.57 66.8 0 bottom
C440  1uF  [0402]  211.45 56.26 270 top
C445  0.1uF  [0402]  244.6 74.04 270 top
C446  10uF  [0603]  251.21 73.66 90 bottom
C447  1uF  [0402]  245.49 69.47 270 bottom
C448  0.1uF  [0402]  248.54 64.14 90 bottom
C449  0.1uF  [0402]  250.44 63.5 90 bottom
C450  0.1uF  [0402]  246.51 64.14 90 bottom
C451  0.1uF  [0402]  244.47 64.14 90 bottom
C454  0.1uF  [0402]  245.62 74.04 270 top
C455  0.1uF  [0402]  249.55 74.04 270 top
C456  0.1uF  [0402]  248.54 74.04 270 top
C457  10uF  [0603]  237.49 62.99 180 bottom
C458  1uF  [0402]  245.49 64.14 90 bottom
C459  0.1uF  [0402]  247.52 64.14 90 bottom
C461  0.1uF  [0402]  242.95 64.26 90 bottom
C462  0.1uF  [0402]  241.94 64.26 90 bottom
C465  10uF  [0603]  255.4 68.83 0 bottom
C466  10uF  [0603]  237.49 69.09 180 bottom
C467  1uF  [0402]  244.47 69.34 270 bottom
C468  0.1uF  [0402]  244.47 65.79 0 bottom
C469  0.1uF  [0402]  246.89 69.72 90 bottom
C470  0.1uF  [0402]  249.17 70.1 90 bottom
C477  10uF  [0603]  255.4 70.74 180 bottom
C478  10uF  [0603]  237.49 67.18 0 bottom
C479  1uF  [0402]  244.73 67.82 0 bottom
C480  0.1uF  [0402]  244.86 66.8 0 bottom
C481  0.1uF  [0402]  248.03 65.66 180 bottom
C482  0.1uF  [0402]  247.9 69.22 90 bottom
C485  1uF  [0402]  245.75 56.26 270 top
C490  0.1uF  [0402]  215.39 38.48 90 bottom
C491  0.1uF  [0402]  249.68 38.48 90 bottom
C492  0.1uF  [0402]  246.76 38.48 90 bottom
C493  0.1uF  [0402]  212.47 38.48 90 bottom
C494  0.1uF  [0402]  243.71 38.48 90 bottom
C495  0.1uF  [0402]  209.42 38.48 90 bottom
C496  0.1uF  [0402]  240.66 38.48 90 bottom
C497  0.1uF  [0402]  206.38 38.48 90 bottom
C498  1000pF  [1206]  237.11 30.86 270 bottom
C499  1000pF  [1206]  202.82 30.86 270 bottom
C500  470pF  [0402]  258.19 63.75 180 top
C501  470pF  [0402]  223.9 63.75 180 top
C502  470pF  [0402]  258.19 62.74 180 top
C503  470pF  [0402]  223.9 62.74 180 top
C504  0.1uF  [0402]  240.79 53.09 90 bottom
C505  0.1uF  [0402]  206.5 53.09 90 bottom
C506  0.1uF  [0402]  237.87 53.09 90 bottom
C507  0.1uF  [0402]  203.58 53.09 90 bottom
C508  0.1uF  [0402]  234.82 53.09 90 bottom
C509  0.1uF  [0402]  200.53 53.09 90 bottom
C510  0.1uF  [0402]  231.77 53.09 90 bottom
C511  0.1uF  [0402]  197.48 53.09 90 bottom
C512  1000pF  [1206]  236.73 39.37 90 bottom
C513  1000pF  [1206]  195.58 41.15 90 bottom
C514  470pF  [0402]  258.19 61.72 180 top
C515  470pF  [0402]  223.9 61.72 180 top
C516  470pF  [0402]  252.48 64.52 90 bottom
C517  470pF  [0402]  218.19 64.52 90 bottom
C518  0.1uF  [0402]  266.95 38.48 90 bottom
C519  0.1uF  [0402]  232.54 38.48 90 bottom
C520  0.1uF  [0402]  263.91 38.48 90 bottom
C521  0.1uF  [0402]  229.62 38.48 90 bottom
C522  0.1uF  [0402]  260.86 38.48 90 bottom
C523  0.1uF  [0402]  226.57 38.48 90 bottom
C524  0.1uF  [0402]  257.81 38.48 90 bottom
C525  0.1uF  [0402]  223.52 38.48 90 bottom
C526  1000pF  [1206]  270.26 29.59 180 bottom
C527  1000pF  [1206]  219.96 30.86 270 bottom
C528  470pF  [0402]  253.87 66.55 270 bottom
C529  470pF  [0402]  219.58 66.55 270 bottom
C530  470pF  [0402]  258.19 66.8 180 top
C531  470pF  [0402]  223.9 66.8 180 top
C532  0.1uF  [0402]  257.94 53.09 90 bottom
C533  0.1uF  [0402]  223.65 53.09 90 bottom
C534  0.1uF  [0402]  255.02 53.09 90 bottom
C535  0.1uF  [0402]  220.73 53.09 90 bottom
C536  0.1uF  [0402]  251.97 53.09 90 bottom
C537  0.1uF  [0402]  217.68 53.09 90 bottom
C538  0.1uF  [0402]  248.92 53.09 90 bottom
C539  0.1uF  [0402]  214.63 53.09 90 bottom
C540  470pF  [0402]  223.9 65.79 180 top
C541  1000pF  [1206]  253.87 39.37 90 bottom
C542  1000pF  [1206]  219.71 39.37 90 bottom
C543  470pF  [0402]  223.9 64.77 180 top
C544  0.01uF  [0402]  272.16 32.26 270 bottom
C545  0.01uF  [0402]  256.29 37.97 180 bottom
C546  470pF  [0402]  258.19 65.79 180 top
C547  470pF  [0402]  258.19 64.77 180 top
C548  0.01uF  [0402]  204.09 35.94 270 bottom
C549  0.1uF  [0402]  261.87 64.77 0 top
C550  0.01uF  [0402]  222 37.97 180 bottom
C551  4.7uF  [0603]  262.51 62.74 90 top
C552  0.01uF  [0402]  263.78 62.48 90 top
C553  0.01uF  [0402]  239.14 37.97 180 bottom
C554  0.1uF  [0402]  170.29 74.06 270 top
C555  0.1uF  [0402]  171.29 74.06 270 top
C556  22uF  [0805]  162.43 66.93 90 bottom
C557  22uF  [0805]  162.43 62.48 270 bottom
C558  1uF  [0402O]  171.29 64.65 270 bottom
C559  1uF  [0402O]  164.29 61.65 270 bottom
C560  1uF  [0402O]  165.29 61.65 270 bottom
C561  1uF  [0402O]  170.29 66.65 270 bottom
C562  1uF  [0402O]  172.29 64.65 90 bottom
C563  1uF  [0402O]  169.29 61.65 270 bottom
C564  0.1uF  [0402]  164.29 74.06 270 top
C565  0.1uF  [0402]  165.29 74.06 270 top
C566  22uF  [0805]  166.62 72.01 180 bottom
C567  22uF  [0805]  171.45 72.01 0 bottom
C568  1uF  [0402O]  164.29 68.65 90 bottom
C569  1uF  [0402O]  166.29 61.65 270 bottom
C570  1uF  [0402O]  174.29 62.65 270 bottom
C571  1uF  [0402O]  167.29 61.65 270 bottom
C572  0.1uF  [0402]  167.26 56.26 270 top
C573  0.1uF  [0402]  168.27 56.26 270 top
C574  0.1uF  [0402]  160.4 69.6 0 top
C575  0.1uF  [0402]  160.4 68.58 0 top
C576  22uF  [0805]  173.86 56.9 270 bottom
C577  1uF  [0402O]  172.29 62.65 90 bottom
C578  22uF  [0805]  177.55 69.22 0 bottom
C579  1uF  [0402O]  172.29 68.65 90 bottom
C580  22uF  [0805]  177.55 67.18 0 bottom
C581  1uF  [0402O]  172.29 66.65 90 bottom
C582  1uF  [0402O]  171.29 66.65 90 bottom
C583  22uF  [0805]  177.55 60.07 0 bottom
C584  1uF  [0402O]  173.29 60.65 270 bottom
C585  1uF  [0402O]  173.29 68.65 90 bottom
C586  0.1uF  [0402]  158.88 65.79 270 bottom
C587  1uF  [0402O]  174.29 60.65 270 bottom
C588  1uF  [0402O]  166.79 63.15 180 bottom
C589  1uF  [0402O]  173.29 64.65 90 bottom
C590  0.1uF  [0402]  179.32 50.93 0 bottom
C591  0.01uF  [0402]  175.26 51.94 180 bottom
C592  22uF  [0805]  180.34 48.51 90 bottom
C593  0.1uF  [0402]  178.31 42.93 0 bottom
C594  0.1uF  [0402]  179.32 51.94 0 bottom
C595  0.01uF  [0402]  175.26 50.93 180 bottom
C596  22uF  [0805]  174.24 48.51 90 bottom
C597  0.1uF  [0402]  176.28 42.93 180 bottom
C598  0.1uF  [0402]  176.91 197.36 180 top
C599  0.1uF  [0402]  176.91 198.37 180 top
C600  10uF  [0603]  191.13 201.06 0 top
C601  10uF  [0603]  77.6 202.29 180 top
C602  0.1uF  [0402]  190.75 189.88 0 top
C603  0.1uF  [0402]  190.75 213.11 0 top
C604  0.1uF  [0402]  77.98 190.25 180 top
C605  0.1uF  [0402]  77.98 213.47 180 top
C606  0.1uF  [0402]  267.21 97.54 180 top
C607  0.1uF  [0402]  267.21 98.55 180 top
C608  0.1uF  [0402]  267.21 101.6 180 top
C609  10uF  [0603]  191.13 199.53 0 top
C610  10uF  [0603]  77.6 203.82 180 top
C611  0.1uF  [0402]  190.75 211.45 0 top
C612  0.1uF  [0402]  190.75 191.53 0 top
C613  0.1uF  [0402]  77.98 211.82 180 top
C614  0.1uF  [0402]  77.98 191.9 180 top
C615  0.1uF  [0402]  267.21 102.62 180 top
C616  0.1uF  [0402]  267.16 105.56 180 top
C617  0.1uF  [0402]  267.16 106.56 180 top
C618  0.1uF  [0402]  267.21 109.6 180 top
C619  0.1uF  [0402]  267.21 110.62 180 top
C620  100uF  [CAPE_B6D3]  264.8 78.99 270 top
C621  10uF  [1206]  269.75 76.2 270 top
C622  10uF  [1206]  272.16 76.2 270 top
C623  0.1uF  [0603]  274.07 77.09 270 top
C624  0.1uF  [0603]  277.11 77.09 270 top
C625  0.1uF  [0603]  275.59 77.09 270 top
C626  10uF  [0603]  266.7 92.33 180 top
C627  0.1uF  [0402]  267.21 91.06 180 top
C628  0.1uF  [0402]  267.21 90.04 180 top
C629  0.1uF  [0402]  267.21 89.03 180 top
C630  0.1uF  [0402]  91.82 205.99 0 top
C631  0.1uF  [0402]  91.82 204.98 0 top
C632  0.01uF  [0402]  250.7 107.82 0 top
C633  0.01uF  [0402]  250.7 108.84 0 top
C634  0.01uF  [0402]  250.7 115.7 0 top
C635  0.01uF  [0402]  250.7 114.68 0 top
C636  0.1uF  [1206]  84.71 40.77 270 bottom
C637  0.068uF  [0805]  93.34 53.59 270 bottom
C638  0.068uF  [0805]  95.5 53.59 270 bottom
C639  0.022uF  [0805]  91.19 49.91 90 bottom
C640  0.022uF  [0805]  89.03 49.91 270 bottom
C641  0.022uF  [0805]  84.45 49.91 90 bottom
C642  0.068uF  [0805]  77.98 53.59 270 bottom
C643  0.022uF  [0805]  82.3 49.91 270 bottom
C644  0.068uF  [0805]  80.14 53.59 270 bottom
C645  0.1uF  [1206]  93.6 40.77 270 bottom
C646  10uF  [0603]  97.41 61.85 180 top
C647  4.7uF  [0603]  96.77 57.53 270 top
C648  4.7uF  [0603]  76.71 57.53 270 top
C649  0.1uF  [0402]  96.77 59.56 0 top
C650  0.1uF  [1206]  86.74 50.55 90 bottom
C651  0.1uF  [1206]  97.79 54.23 90 bottom
C652  4.7uF  [0603]  84.45 62.61 0 bottom
C653  0.1uF  [0402]  90.93 62.61 0 bottom
C654  0.1uF  [0402]  81.92 62.48 180 bottom
C655  0.1uF  [0402]  82.8 53.34 0 bottom
C656  0.1uF  [0402]  82.8 54.61 0 bottom
C657  0.1uF  [0402]  90.68 54.61 180 bottom
C658  0.1uF  [1206]  102.49 40.77 270 bottom
C659  0.068uF  [0805]  116.2 53.59 270 bottom
C660  0.068uF  [0805]  118.36 53.59 270 bottom
C661  0.022uF  [0805]  114.05 49.91 90 bottom
C662  0.022uF  [0805]  111.89 49.91 270 bottom
C664  0.022uF  [0805]  107.32 49.91 90 bottom
C666  0.068uF  [0805]  100.84 53.59 270 bottom
C667  0.022uF  [0805]  105.16 49.91 270 bottom
C668  0.068uF  [0805]  103 53.59 270 bottom
C669  0.1uF  [1206]  111.38 40.77 270 bottom
C670  10uF  [0603]  120.27 61.85 180 top
C671  4.7uF  [0603]  119.63 57.53 270 top
C672  4.7uF  [0603]  99.57 57.53 270 top
C673  0.1uF  [0402]  119.63 59.56 0 top
C674  0.1uF  [1206]  109.6 50.55 90 bottom
C675  0.1uF  [1206]  120.65 54.23 90 bottom
C676  4.7uF  [0603]  107.32 62.61 0 bottom
C677  0.1uF  [0402]  113.79 62.61 0 bottom
C678  0.1uF  [0402]  104.78 62.48 180 bottom
C679  0.1uF  [0402]  113.54 54.61 180 bottom
C680  0.1uF  [0402]  105.66 53.34 0 bottom
C681  0.1uF  [0402]  105.66 54.61 0 bottom
C682  4700pF  [0402]  97.92 65.28 90 top
C683  4.7pF  [0402]  96.39 65.79 0 top
C684  330pF  [0402]  94.87 65.28 90 top
C685  0.1uF  [1206]  35.05 75.31 90 top
C686  0.1uF  [0603]  59.56 43.81 0 top
C687  470uF  [CAPE_P5_B10]  68.33 41.66 270 top
C688  0.1uF  [0603]  62.36 45.09 270 top
C689  100uF  [CAPE_P5_B12D5]  41.02 56.9 270 top
C690  1000pF  [0603]  64.14 53.98 90 bottom
C691  82uF  [CAPE_P3D5_B8]  50.55 65.15 180 top
C692  82uF  [CAPE_P3D5_B8]  50.55 74.04 180 top
C693  1uF  [1206]  44.2 75.31 90 top
C694  0.1uF  [1206]  41.66 75.31 90 top
C695  0.1uF  [0603]  72.01 61.85 180 bottom
C696  470pF  [0402]  77.6 66.04 0 bottom
C697  220pF  [0402]  93.34 66.8 180 top
C698  1uF  [0402O]  65.52 106.93 180 bottom
C699  0.1uF  [0402O]  63.52 105.93 0 bottom
C700  0.1uF  [0402O]  63.52 106.93 180 bottom
C701  0.1uF  [0402]  47.37 110.36 0 top
C702  0.01uF  [0402]  47.37 111.38 0 top
C703  1uF  [0402]  50.16 114.3 90 top
C704  0.1uF  [0402]  51.18 114.3 90 top
C705  1uF  [0402O]  57.51 112.93 0 bottom
C706  0.1uF  [0402O]  62.51 107.93 0 bottom
C707  0.1uF  [0402O]  57.51 99.92 0 bottom
C708  0.1uF  [0402O]  57.51 98.92 180 bottom
C709  0.1uF  [0402O]  62.51 104.92 0 bottom
C710  0.1uF  [0402O]  71.52 98.92 0 bottom
C711  1uF  [0402O]  64.02 108.43 270 bottom
C712  0.1uF  [0402O]  65.02 108.43 270 bottom
C713  0.1uF  [0402O]  71.52 99.92 180 bottom
C714  0.1uF  [0402O]  66.52 107.93 180 bottom
C715  0.1uF  [0402O]  57.51 113.93 180 bottom
C716  0.1uF  [0402O]  66.52 104.92 180 bottom
C718  10pF  [0402]  89.79 98.93 0 top
C720  0.1uF  [0402]  78.87 96.65 270 top
C721  0.01uF  [0402]  77.85 96.65 270 top
C722  1uF  [0402]  79.38 100.84 90 top
C723  0.1uF  [0402]  80.39 100.84 90 top
C728  10pF  [0402]  89.79 107.19 0 top
C729  0.1uF  [0402]  79.38 103.63 270 top
C730  0.01uF  [0402]  78.36 103.63 270 top
C731  1uF  [0402]  83.57 110.36 90 top
C732  0.1uF  [0402]  84.58 110.36 90 top
C733  2pF  [0402]  234.44 132.59 180 top
C734  2pF  [0402]  236.47 132.59 0 top
C735  0.1uF  [0402]  238.89 133.86 180 bottom
C736  10uF  [0603]  237.36 141.22 0 bottom
C737  0.01uF  [0402]  236.6 138.94 270 bottom
C738  33pF  [0402]  156.08 62.86 180 top
C739  27pF  [0402]  153.92 62.86 0 top
C740  27pF  [0402]  231.14 67.95 0 top
C741  33pF  [0402]  233.3 67.95 0 top
C742  0.1uF  [0402]  157.1 66.8 270 top
C743  0.1uF  [0402]  149.61 62.86 0 top
C744  0.1uF  [0402]  228.22 67.95 0 top
C745  0.1uF  [0402]  236.09 72.26 270 top
C746  0.1uF  [0402]  155.7 71.63 0 top
C747  0.1uF  [0402]  147.45 68.96 270 top
C748  0.1uF  [0402]  234.57 76.71 0 top
C749  0.1uF  [0402]  230.76 76.71 0 top
C750  10uF  [0603]  146.43 64.26 180 top
C751  0.01uF  [0402]  146.94 65.53 180 top
C752  10uF  [0603]  225.42 70.23 180 top
C753  0.01uF  [0402]  225.93 71.5 180 top
C754  10uF  [1206]  100.58 98.3 180 top
C755  22uF  [1210]  100.46 103.12 180 bottom
C756  0.22uF  [0402]  106.05 100.08 0 top
C757  10uF  [1206]  100.46 96.52 180 bottom
C758  22uF  [1210]  100.46 93.47 180 bottom
C759  220uF  [CAPE_B8]  96.52 104.01 180 top
C760  1uF  [0402]  102.11 89.03 90 bottom
C761  0.01uF  [0402]  96.27 80.65 270 bottom
C762  0.1uF  [0402]  101.09 89.03 90 bottom
C763  0.22uF  [0402]  103 92.33 90 top
C764  3000pF  [0402]  103.38 78.61 270 bottom
C765  0.22uF  [0402]  109.6 84.45 270 bottom
C766  1000pF  [0603]  111.38 89.03 0 top
C767  470uF  [7343]  128.78 106.93 180 top
C768  470uF  [7343]  128.02 101.85 0 top
C769  0.22uF  [0402]  106.05 89.92 0 top
C770  0.01uF  [0402]  93.73 84.2 0 bottom
C771  10uF  [1206]  104.65 111 90 top
C772  10uF  [1206]  100.46 106.17 180 bottom
C773  22uF  [1210]  100.46 99.57 180 bottom
C774  22uF  [1210]  100.46 109.22 180 bottom
C775  220uF  [CAPE_B8]  96.52 92.58 180 top
C776  470uF  [7343]  128.02 96.77 0 top
C777  470uF  [7343]  128.02 91.69 0 top
C778  100pF  [0402]  106.55 82.04 270 bottom
C779  0.22uF  [0402]  103 102.49 90 top
C781  22uF  [0805]  130.43 92.08 0 bottom
C782  22uF  [0805]  123.57 112.4 180 bottom
C783  22uF  [0805]  130.43 102.23 0 bottom
C784  22uF  [0805]  130.43 98.17 0 bottom
C785  0.22uF  [0402]  109.6 86.49 270 bottom
C786  1000pF  [0603]  111.38 109.6 0 top
C787  22uF  [0805]  130.43 100.2 0 bottom
C788  22uF  [0805]  123.57 114.43 180 bottom
C789  22uF  [0805]  127.51 90.42 270 bottom
C790  22uF  [0805]  130.43 94.11 0 bottom
C791  22uF  [0805]  123.44 90.42 270 bottom
C792  22uF  [0805]  130.43 96.14 0 bottom
C793  22uF  [0805]  123.57 110.36 180 bottom
C794  22uF  [0805]  125.48 90.42 270 bottom
C795  4.7uF  [0603]  99.57 78.11 270 bottom
C796  1uF  [0603]  86.74 82.04 180 top
C797  10uF  [0805]  87 80.26 180 top
C798  1uF  [0603]  86.74 83.57 0 top
C871  0.01uF  [0402]  129.79 114.94 180 top
C873  0.01uF  [0402]  41.78 102.36 270 top
C874  0.01uF  [0402]  20.07 73.91 270 top
C875  0.01uF  [0402]  79.25 81.41 270 top
C876  0.01uF  [0402]  41.78 93.98 270 top
C878  0.01uF  [0402]  44.83 121.41 90 top
C879  0.01uF  [0402]  51.18 121.41 270 top
C880  10uF  [0603]  230.12 152.4 0 top
C881  10uF  [0603]  230.12 150.88 0 top
C882  4.7uF  [0603]  230.38 144.65 90 top
C883  0.1uF  [0402]  224.54 145.29 90 top
C884  1uF  [0402]  224.54 148.08 270 top
C885  22uF  [0805]  226.19 151.13 180 top
C886  22uF  [0805]  226.19 153.29 180 top
C887  1000pF  [0402]  230.12 148.08 270 top
C888  10uF  [0603]  75.31 151.38 270 top
C889  10uF  [0603]  72.64 148.21 180 top
C890  10uF  [1206]  60.45 135.64 270 top
C891  0.1uF  [0603]  62.36 134.75 270 top
C892  22pF  [0402]  52.32 133.1 90 top
C893  0.1uF  [0402]  18.67 61.72 0 top
C894  0.1uF  [0402]  14.35 70.23 90 top
C895  0.1uF  [0402]  15.75 64.26 0 top
C896  0.1uF  [0402]  7.11 63.37 270 top
